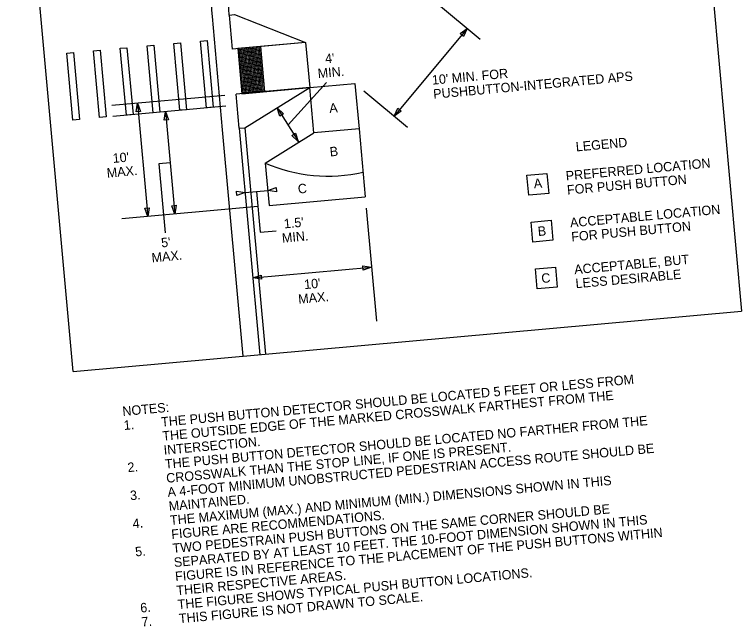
# Model space of a CAD drawing. Extents: x 1277218 to 1279252, y 196905 to 197529.
# Drawn here: x 1278337.8 to 1278669.3, y 196934.2 to 197213 of the extents above; entities that cross this region are included whole.
import ezdxf

# ---------------------------------------------------------------- set-up
doc = ezdxf.new("R2010")
doc.units = 0
doc.layers.add('C-TOPO-SURF-VOID', color=7, linetype='Continuous')

msp = doc.modelspace()

# ---------------------------------------------------------------- linework, layer by layer
at = {"layer": 'C-TOPO-SURF-VOID'}
for p, q in [((1278642.58, 197372.36), (1278669.26, 197077.94)), ((1278364.51, 197050.32), (1278337.83, 197344.75)), ((1278530.19, 197218.42), (1278550.08, 197201.84)), ((1278435.61, 197212.8), (1278438.19, 197213.04)), ((1278438.19, 197213.04), (1278470.54, 197200.37)), ((1278427.87, 197212.1), (1278432.54, 197160.51)), ((1278435.61, 197212.8), (1278437.01, 197197.33)), ((1278544.26, 197206.69), (1278510.91, 197166.7)), ((1278470.54, 197200.37), (1278437.01, 197197.33)), ((1278470.54, 197200.37), (1278439.59, 197197.56)), ((1278470.54, 197200.37), (1278472.41, 197179.73)), ((1278439.59, 197197.56), (1278441.46, 197176.92)), ((1278449.91, 197198.5), (1278451.78, 197177.86)), ((1278462.51, 197162.71), (1278480.12, 197182.07)), ((1278472.41, 197179.73), (1278438.88, 197176.69)), ((1278440.28, 197161.21), (1278438.88, 197176.69)), ((1278441.46, 197176.92), (1278472.41, 197179.73)), ((1278442.86, 197161.45), (1278472.41, 197179.73)), ((1278497.05, 197178.26), (1278516.94, 197161.68)), ((1278433.72, 197176.22), (1278382.13, 197171.55)), ((1278434.17, 197171.3), (1278382.58, 197166.63)), ((1278393.93, 197172.62), (1278398.61, 197121.03)), ((1278457.64, 197170.59), (1278467.39, 197154.83)), ((1278406.66, 197168.81), (1278410.89, 197122.14)), ((1278432.54, 197160.51), (1278441.89, 197057.33)), ((1278440.28, 197161.21), (1278442.86, 197161.45)), ((1278440.28, 197161.21), (1278449.63, 197058.03)), ((1278442.86, 197161.45), (1278452.21, 197058.27)), ((1278494.92, 197160.96), (1278497.72, 197130.01)), ((1278452.12, 197145.38), (1278474.28, 197159.09)), ((1278452.12, 197145.38), (1278453.87, 197126.04)), ((1278442.94, 197131.92), (1278453.26, 197132.85)), ((1278453.87, 197126.04), (1278497.72, 197130.01)), ((1278448.71, 197125.57), (1278386.81, 197119.96)), ((1278498.19, 197124.85), (1278502.87, 197073.26)), ((1278446.46, 197093.01), (1278500.63, 197097.92)), ((1278364.51, 197050.32), (1278669.26, 197077.94))]:
    msp.add_line(p, q, dxfattribs=at)
for points in [[(1278541.03, 197204.33), (1278544.26, 197206.69), (1278542.52, 197203.09)], [(1278410.43, 197199.88), (1278413.48, 197200.15), (1278416.24, 197169.68), (1278413.19, 197169.4)], [(1278422.62, 197200.98), (1278425.67, 197201.26), (1278428.43, 197170.78), (1278425.38, 197170.51)], [(1278373.86, 197196.56), (1278376.91, 197196.84), (1278379.67, 197166.37), (1278376.62, 197166.09)], [(1278386.05, 197197.67), (1278389.1, 197197.94), (1278391.86, 197167.47), (1278388.81, 197167.19)], [(1278398.24, 197198.77), (1278401.29, 197199.05), (1278404.05, 197168.57), (1278401, 197168.3)], [(1278361.67, 197195.46), (1278364.72, 197195.74), (1278367.48, 197165.26), (1278364.43, 197164.98)], [(1278472.41, 197179.73), (1278493.05, 197181.6), (1278494.92, 197160.96), (1278474.28, 197159.09)], [(1278393.32, 197168.66), (1278393.93, 197172.62), (1278395.25, 197168.84)], [(1278458.86, 197166.77), (1278457.64, 197170.59), (1278460.51, 197167.8)], [(1278514.15, 197169.06), (1278510.91, 197166.7), (1278512.66, 197170.31)], [(1278406.05, 197164.85), (1278406.66, 197168.81), (1278407.98, 197165.03)], [(1278465.97, 197158.96), (1278467.19, 197155.15), (1278464.32, 197157.94)], [(1278571.42, 197139.81), (1278580.57, 197140.64), (1278581.39, 197131.5), (1278572.25, 197130.67)], [(1278457.21, 197132.23), (1278453.26, 197132.85), (1278457.04, 197134.17)], [(1278438.98, 197132.53), (1278442.94, 197131.92), (1278439.16, 197130.6)], [(1278399.22, 197124.98), (1278398.61, 197121.03), (1278397.29, 197124.81)], [(1278411.51, 197126.1), (1278410.89, 197122.14), (1278409.57, 197125.92)], [(1278573.36, 197118.48), (1278582.5, 197119.31), (1278583.33, 197110.17), (1278574.19, 197109.34)], [(1278496.68, 197098.54), (1278500.63, 197097.92), (1278496.85, 197096.6)], [(1278575.29, 197097.15), (1278584.43, 197097.98), (1278585.26, 197088.83), (1278576.12, 197088)], [(1278450.42, 197092.4), (1278446.46, 197093.01), (1278450.24, 197094.33)]]:
    msp.add_lwpolyline(points, close=True, dxfattribs=at)
for points in [[(1278408.78, 197145.48), (1278403.62, 197145.01), (1278406.46, 197113.63)], [(1278448.1, 197132.38), (1278449.78, 197113.86), (1278457.07, 197114.52)]]:
    msp.add_lwpolyline(points, dxfattribs=at)
for centre in [(1278440.25, 197197.05), (1278440.31, 197196.44), (1278440.86, 197197.1), (1278440.92, 197196.49), (1278441.47, 197197.16), (1278441.52, 197196.55), (1278442.08, 197197.21), (1278442.13, 197196.61), (1278442.69, 197197.27), (1278442.74, 197196.66), (1278443.3, 197197.33), (1278443.35, 197196.72), (1278443.91, 197197.38), (1278443.96, 197196.77), (1278444.52, 197197.44), (1278444.57, 197196.83), (1278444.63, 197196.22), (1278445.13, 197197.49), (1278445.18, 197196.88), (1278445.24, 197196.27), (1278445.74, 197197.55), (1278445.79, 197196.94), (1278445.85, 197196.33), (1278446.35, 197197.6), (1278446.4, 197196.99), (1278446.46, 197196.38), (1278446.95, 197197.66), (1278447.01, 197197.05), (1278447.07, 197196.44), (1278447.56, 197197.71), (1278447.62, 197197.1), (1278447.67, 197196.49), (1278448.17, 197197.77), (1278448.23, 197197.16), (1278448.28, 197196.55), (1278448.78, 197197.82), (1278448.84, 197197.21), (1278448.89, 197196.6), (1278449.39, 197197.88), (1278449.45, 197197.27), (1278449.5, 197196.66), (1278440.36, 197195.83), (1278440.42, 197195.22), (1278440.47, 197194.61), (1278440.53, 197194), (1278440.58, 197193.39), (1278440.97, 197195.89), (1278441.03, 197195.28), (1278441.08, 197194.67), (1278441.14, 197194.06), (1278441.19, 197193.45), (1278441.58, 197195.94), (1278441.63, 197195.33), (1278441.69, 197194.72), (1278441.75, 197194.11), (1278441.8, 197193.5), (1278441.86, 197192.89), (1278442.19, 197196), (1278442.24, 197195.39), (1278442.3, 197194.78), (1278442.35, 197194.17), (1278442.41, 197193.56), (1278442.47, 197192.95), (1278442.8, 197196.05), (1278442.85, 197195.44), (1278442.91, 197194.83), (1278442.96, 197194.22), (1278443.02, 197193.61), (1278443.07, 197193), (1278443.41, 197196.11), (1278443.46, 197195.5), (1278443.52, 197194.89), (1278443.57, 197194.28), (1278443.63, 197193.67), (1278443.68, 197193.06), (1278444.02, 197196.16), (1278444.07, 197195.55), (1278444.13, 197194.94), (1278444.18, 197194.33), (1278444.24, 197193.72), (1278444.29, 197193.11), (1278444.68, 197195.61), (1278444.74, 197195), (1278444.79, 197194.39), (1278444.85, 197193.78), (1278444.9, 197193.17), (1278445.29, 197195.66), (1278445.35, 197195.05), (1278445.4, 197194.44), (1278445.46, 197193.83), (1278445.51, 197193.22), (1278445.9, 197195.72), (1278445.96, 197195.11), (1278446.01, 197194.5), (1278446.07, 197193.89), (1278446.12, 197193.28), (1278446.51, 197195.77), (1278446.57, 197195.16), (1278446.62, 197194.55), (1278446.68, 197193.94), (1278446.73, 197193.34), (1278447.12, 197195.83), (1278447.18, 197195.22), (1278447.23, 197194.61), (1278447.29, 197194), (1278447.34, 197193.39), (1278447.73, 197195.88), (1278447.79, 197195.27), (1278447.84, 197194.66), (1278447.9, 197194.06), (1278447.95, 197193.45), (1278448.34, 197195.94), (1278448.39, 197195.33), (1278448.45, 197194.72), (1278448.51, 197194.11), (1278448.56, 197193.5), (1278448.62, 197192.89), (1278448.95, 197195.99), (1278449, 197195.38), (1278449.06, 197194.78), (1278449.11, 197194.17), (1278449.17, 197193.56), (1278449.23, 197192.95), (1278449.56, 197196.05), (1278449.61, 197195.44), (1278449.67, 197194.83), (1278449.72, 197194.22), (1278449.78, 197193.61), (1278449.83, 197193), (1278440.64, 197192.78), (1278440.69, 197192.17), (1278440.75, 197191.56), (1278440.8, 197190.95), (1278440.86, 197190.34), (1278440.91, 197189.74), (1278441.25, 197192.84), (1278441.3, 197192.23), (1278441.36, 197191.62), (1278441.41, 197191.01), (1278441.47, 197190.4), (1278441.52, 197189.79), (1278441.91, 197192.28), (1278441.97, 197191.67), (1278442.02, 197191.06), (1278442.08, 197190.46), (1278442.13, 197189.85), (1278442.52, 197192.34), (1278442.58, 197191.73), (1278442.63, 197191.12), (1278442.69, 197190.51), (1278442.74, 197189.9), (1278443.13, 197192.39), (1278443.19, 197191.78), (1278443.24, 197191.18), (1278443.3, 197190.57), (1278443.35, 197189.96), (1278443.74, 197192.45), (1278443.79, 197191.84), (1278443.85, 197191.23), (1278443.91, 197190.62), (1278443.96, 197190.01), (1278444.35, 197192.5), (1278444.4, 197191.9), (1278444.46, 197191.29), (1278444.51, 197190.68), (1278444.57, 197190.07), (1278444.96, 197192.56), (1278445.01, 197191.95), (1278445.07, 197191.34), (1278445.12, 197190.73), (1278445.18, 197190.12), (1278445.57, 197192.62), (1278445.62, 197192.01), (1278445.68, 197191.4), (1278445.73, 197190.79), (1278445.79, 197190.18), (1278445.84, 197189.57), (1278446.18, 197192.67), (1278446.23, 197192.06), (1278446.29, 197191.45), (1278446.34, 197190.84), (1278446.4, 197190.23), (1278446.45, 197189.62), (1278446.79, 197192.73), (1278446.84, 197192.12), (1278446.9, 197191.51), (1278446.95, 197190.9), (1278447.01, 197190.29), (1278447.06, 197189.68), (1278447.4, 197192.78), (1278447.45, 197192.17), (1278447.51, 197191.56), (1278447.56, 197190.95), (1278447.62, 197190.34), (1278447.67, 197189.73), (1278448.01, 197192.84), (1278448.06, 197192.23), (1278448.12, 197191.62), (1278448.17, 197191.01), (1278448.23, 197190.4), (1278448.28, 197189.79), (1278448.67, 197192.28), (1278448.73, 197191.67), (1278448.78, 197191.06), (1278448.84, 197190.45), (1278448.89, 197189.84), (1278449.28, 197192.34), (1278449.34, 197191.73), (1278449.39, 197191.12), (1278449.45, 197190.51), (1278449.5, 197189.9), (1278449.89, 197192.39), (1278449.95, 197191.78), (1278450, 197191.17), (1278450.06, 197190.56), (1278450.11, 197189.95), (1278440.97, 197189.13), (1278441.02, 197188.52), (1278441.08, 197187.91), (1278441.13, 197187.3), (1278441.19, 197186.69), (1278441.58, 197189.18), (1278441.63, 197188.57), (1278441.69, 197187.96), (1278441.74, 197187.35), (1278441.8, 197186.74), (1278442.19, 197189.24), (1278442.24, 197188.63), (1278442.3, 197188.02), (1278442.35, 197187.41), (1278442.41, 197186.8), (1278442.8, 197189.29), (1278442.85, 197188.68), (1278442.91, 197188.07), (1278442.96, 197187.46), (1278443.02, 197186.85), (1278443.41, 197189.35), (1278443.46, 197188.74), (1278443.52, 197188.13), (1278443.57, 197187.52), (1278443.63, 197186.91), (1278443.68, 197186.3), (1278444.02, 197189.4), (1278444.07, 197188.79), (1278444.13, 197188.18), (1278444.18, 197187.57), (1278444.24, 197186.96), (1278444.29, 197186.35), (1278444.63, 197189.46), (1278444.68, 197188.85), (1278444.74, 197188.24), (1278444.79, 197187.63), (1278444.85, 197187.02), (1278444.9, 197186.41), (1278445.23, 197189.51), (1278445.29, 197188.9), (1278445.35, 197188.29), (1278445.4, 197187.68), (1278445.46, 197187.07), (1278445.51, 197186.46), (1278445.9, 197188.96), (1278445.95, 197188.35), (1278446.01, 197187.74), (1278446.07, 197187.13), (1278446.12, 197186.52), (1278446.51, 197189.01), (1278446.56, 197188.4), (1278446.62, 197187.79), (1278446.67, 197187.18), (1278446.73, 197186.58), (1278447.12, 197189.07), (1278447.17, 197188.46), (1278447.23, 197187.85), (1278447.28, 197187.24), (1278447.34, 197186.63), (1278447.73, 197189.12), (1278447.78, 197188.51), (1278447.84, 197187.9), (1278447.89, 197187.3), (1278447.95, 197186.69), (1278448.34, 197189.18), (1278448.39, 197188.57), (1278448.45, 197187.96), (1278448.5, 197187.35), (1278448.56, 197186.74), (1278448.95, 197189.23), (1278449, 197188.62), (1278449.06, 197188.02), (1278449.11, 197187.41), (1278449.17, 197186.8), (1278449.56, 197189.29), (1278449.61, 197188.68), (1278449.67, 197188.07), (1278449.72, 197187.46), (1278449.78, 197186.85), (1278450.17, 197189.34), (1278450.22, 197188.74), (1278450.28, 197188.13), (1278450.33, 197187.52), (1278450.39, 197186.91), (1278450.44, 197186.3), (1278441.24, 197186.08), (1278441.3, 197185.47), (1278441.35, 197184.86), (1278441.41, 197184.25), (1278441.47, 197183.64), (1278441.52, 197183.03), (1278441.85, 197186.13), (1278441.91, 197185.52), (1278441.96, 197184.91), (1278442.02, 197184.31), (1278442.07, 197183.7), (1278442.13, 197183.09), (1278442.46, 197186.19), (1278442.52, 197185.58), (1278442.57, 197184.97), (1278442.63, 197184.36), (1278442.68, 197183.75), (1278442.74, 197183.14), (1278443.07, 197186.24), (1278443.13, 197185.63), (1278443.18, 197185.03), (1278443.24, 197184.42), (1278443.29, 197183.81), (1278443.35, 197183.2), (1278443.74, 197185.69), (1278443.79, 197185.08), (1278443.85, 197184.47), (1278443.9, 197183.86), (1278443.96, 197183.25), (1278444.35, 197185.75), (1278444.4, 197185.14), (1278444.46, 197184.53), (1278444.51, 197183.92), (1278444.57, 197183.31), (1278444.96, 197185.8), (1278445.01, 197185.19), (1278445.07, 197184.58), (1278445.12, 197183.97), (1278445.18, 197183.36), (1278445.57, 197185.86), (1278445.62, 197185.25), (1278445.68, 197184.64), (1278445.73, 197184.03), (1278445.79, 197183.42), (1278446.18, 197185.91), (1278446.23, 197185.3), (1278446.29, 197184.69), (1278446.34, 197184.08), (1278446.4, 197183.47), (1278446.79, 197185.97), (1278446.84, 197185.36), (1278446.9, 197184.75), (1278446.95, 197184.14), (1278447.01, 197183.53), (1278447.39, 197186.02), (1278447.45, 197185.41), (1278447.51, 197184.8), (1278447.56, 197184.19), (1278447.62, 197183.58), (1278447.67, 197182.97), (1278448, 197186.08), (1278448.06, 197185.47), (1278448.11, 197184.86), (1278448.17, 197184.25), (1278448.23, 197183.64), (1278448.28, 197183.03), (1278448.61, 197186.13), (1278448.67, 197185.52), (1278448.72, 197184.91), (1278448.78, 197184.3), (1278448.83, 197183.69), (1278448.89, 197183.08), (1278449.22, 197186.19), (1278449.28, 197185.58), (1278449.33, 197184.97), (1278449.39, 197184.36), (1278449.44, 197183.75), (1278449.5, 197183.14), (1278449.83, 197186.24), (1278449.89, 197185.63), (1278449.94, 197185.02), (1278450, 197184.41), (1278450.05, 197183.8), (1278450.11, 197183.19), (1278450.5, 197185.69), (1278450.55, 197185.08), (1278450.61, 197184.47), (1278450.66, 197183.86), (1278450.72, 197183.25), (1278441.58, 197182.42), (1278441.63, 197181.81), (1278441.69, 197181.2), (1278441.74, 197180.59), (1278441.8, 197179.98), (1278442.19, 197182.48), (1278442.24, 197181.87), (1278442.3, 197181.26), (1278442.35, 197180.65), (1278442.41, 197180.04), (1278442.79, 197182.53), (1278442.85, 197181.92), (1278442.91, 197181.31), (1278442.96, 197180.7), (1278443.02, 197180.09), (1278443.4, 197182.59), (1278443.46, 197181.98), (1278443.51, 197181.37), (1278443.57, 197180.76), (1278443.63, 197180.15), (1278444.01, 197182.64), (1278444.07, 197182.03), (1278444.12, 197181.42), (1278444.18, 197180.81), (1278444.23, 197180.2), (1278444.62, 197182.7), (1278444.68, 197182.09), (1278444.73, 197181.48), (1278444.79, 197180.87), (1278444.84, 197180.26), (1278444.9, 197179.65), (1278445.23, 197182.75), (1278445.29, 197182.14), (1278445.34, 197181.53), (1278445.4, 197180.92), (1278445.45, 197180.31), (1278445.51, 197179.71), (1278445.84, 197182.81), (1278445.9, 197182.2), (1278445.95, 197181.59), (1278446.01, 197180.98), (1278446.06, 197180.37), (1278446.12, 197179.76), (1278446.45, 197182.86), (1278446.51, 197182.25), (1278446.56, 197181.64), (1278446.62, 197181.03), (1278446.67, 197180.43), (1278446.73, 197179.82), (1278447.06, 197182.92), (1278447.12, 197182.31), (1278447.17, 197181.7), (1278447.23, 197181.09), (1278447.28, 197180.48), (1278447.34, 197179.87), (1278447.73, 197182.36), (1278447.78, 197181.75), (1278447.84, 197181.15), (1278447.89, 197180.54), (1278447.95, 197179.93), (1278448.34, 197182.42), (1278448.39, 197181.81), (1278448.45, 197181.2), (1278448.5, 197180.59), (1278448.56, 197179.98), (1278448.95, 197182.47), (1278449, 197181.87), (1278449.06, 197181.26), (1278449.11, 197180.65), (1278449.17, 197180.04), (1278449.55, 197182.53), (1278449.61, 197181.92), (1278449.66, 197181.31), (1278449.72, 197180.7), (1278449.78, 197180.09), (1278450.16, 197182.59), (1278450.22, 197181.98), (1278450.27, 197181.37), (1278450.33, 197180.76), (1278450.38, 197180.15), (1278450.77, 197182.64), (1278450.83, 197182.03), (1278450.88, 197181.42), (1278450.94, 197180.81), (1278450.99, 197180.2), (1278441.85, 197179.37), (1278441.91, 197178.76), (1278441.96, 197178.15), (1278442.02, 197177.55), (1278442.46, 197179.43), (1278442.52, 197178.82), (1278442.57, 197178.21), (1278442.63, 197177.6), (1278443.07, 197179.48), (1278443.13, 197178.87), (1278443.18, 197178.27), (1278443.24, 197177.66), (1278443.68, 197179.54), (1278443.74, 197178.93), (1278443.79, 197178.32), (1278443.85, 197177.71), (1278444.29, 197179.59), (1278444.35, 197178.99), (1278444.4, 197178.38), (1278444.46, 197177.77), (1278444.95, 197179.04), (1278445.01, 197178.43), (1278445.07, 197177.82), (1278445.56, 197179.1), (1278445.62, 197178.49), (1278445.67, 197177.88), (1278446.17, 197179.15), (1278446.23, 197178.54), (1278446.28, 197177.93), (1278446.78, 197179.21), (1278446.84, 197178.6), (1278446.89, 197177.99), (1278447.39, 197179.26), (1278447.45, 197178.65), (1278447.5, 197178.04), (1278448, 197179.32), (1278448.06, 197178.71), (1278448.11, 197178.1), (1278448.61, 197179.37), (1278448.67, 197178.76), (1278448.72, 197178.15), (1278449.22, 197179.43), (1278449.28, 197178.82), (1278449.33, 197178.21), (1278449.83, 197179.48), (1278449.89, 197178.87), (1278449.94, 197178.26), (1278450.44, 197179.54), (1278450.5, 197178.93), (1278450.55, 197178.32), (1278451.05, 197179.59), (1278451.1, 197178.98), (1278451.16, 197178.37)]:
    msp.add_circle(centre, 0.115, dxfattribs=at)
for centre, radius, start, end in [((1278489.74, 197218.08), 62.16, 94.7692, 185.5865), ((1278489.74, 197218.08), 54.39, 94.7692, 185.5865), ((1278480.87, 197211.93), 72.5, 246.6378, 282.6239)]:
    msp.add_arc(centre, radius, start, end, dxfattribs=at)

# ---------------------------------------------------------------- texts
for s, height, p in [("4'", 4.284, (1278479.61, 197190.78)), ('MIN.', 4.284, (1278476.25, 197184.02)), ("10' MIN. FOR ", 4.2839, (1278528.33, 197181.07)), ('PUSHBUTTON-INTEGRATED APS', 4.2839, (1278528.91, 197174.67)), ('A', 4.28, (1278481.5, 197168.21)), ('LEGEND', 4.284, (1278593.91, 197150.64)), ("10'", 4.284, (1278382.76, 197145.38)), ('B', 4.28, (1278481.73, 197148.35)), ('PREFERRED LOCATION ', 4.2839, (1278589.35, 197137.37)), ('MAX.', 4.284, (1278380.06, 197138.69)), ('FOR PUSH BUTTON', 4.2839, (1278589.93, 197130.97)), ('A', 4.28, (1278574.72, 197133.81)), ('C', 4.28, (1278467.19, 197131.43)), ('ACCEPTABLE LOCATION ', 4.2839, (1278591.28, 197116.03)), ("1.5'", 4.284, (1278460.81, 197115.58)), ('FOR PUSH BUTTON', 4.2839, (1278591.86, 197109.63)), ('MIN.', 4.284, (1278459.93, 197109.05)), ('B', 4.28, (1278576.58, 197112.08)), ("5'", 4.284, (1278404.86, 197106.91)), ('MAX.', 4.284, (1278400.5, 197100.06)), ('ACCEPTABLE, BUT ', 4.2839, (1278593.21, 197094.7)), ('LESS DESIRABLE', 4.2839, (1278593.79, 197088.3)), ('C', 4.28, (1278578.2, 197090.66)), ("10'", 4.284, (1278470.06, 197087.9)), ('MAX.', 4.284, (1278467.36, 197081.21)), ('THE PUSH BUTTON DETECTOR SHOULD BE LOCATED 5 FEET OR LESS FROM ', 4.2839, (1278404.86, 197025.24)), ('THE OUTSIDE EDGE OF THE MARKED CROSSWALK FARTHEST FROM THE ', 4.2839, (1278405.44, 197018.84)), ('NOTES:', 4.284, (1278387.21, 197030.1)), ('1.', 4.284, (1278387.79, 197023.7)), ('THE PUSH BUTTON DETECTOR SHOULD BE LOCATED NO FARTHER FROM THE ', 4.2839, (1278406.6, 197006.04)), ('INTERSECTION.', 4.2839, (1278406.02, 197012.44)), ('CROSSWALK THAN THE STOP LINE, IF ONE IS PRESENT.', 4.2839, (1278407.18, 196999.64)), ('A 4-FOOT MINIMUM UNOBSTRUCTED PEDESTRIAN ACCESS ROUTE SHOULD BE ', 4.2839, (1278407.76, 196993.24)), ('2.', 4.284, (1278389.53, 197004.5)), ('THE MAXIMUM (MAX.) AND MINIMUM (MIN.) DIMENSIONS SHOWN IN THIS ', 4.2839, (1278408.92, 196980.45)), ('3.', 4.284, (1278390.69, 196991.7)), ('MAINTAINED.', 4.2839, (1278408.34, 196986.85)), ('TWO PEDESTRAIN PUSH BUTTONS ON THE SAME CORNER SHOULD BE ', 4.2839, (1278410.08, 196967.65)), ('FIGURE ARE RECOMMENDATIONS.', 4.2839, (1278409.5, 196974.05)), ('SEPARATED BY AT LEAST 10 FEET. THE 10-FOOT DIMENSION SHOWN IN THIS ', 4.2839, (1278410.66, 196961.25)), ('4.', 4.284, (1278391.85, 196978.9)), ('FIGURE IS IN REFERENCE TO THE PLACEMENT OF THE PUSH BUTTONS WITHIN ', 4.2839, (1278411.24, 196954.85)), ('5.', 4.284, (1278393.01, 196966.1)), ('THEIR RESPECTIVE AREAS.', 4.2839, (1278411.82, 196948.45)), ('THE FIGURE SHOWS TYPICAL PUSH BUTTON LOCATIONS.', 4.2839, (1278412.4, 196942.05)), ('THIS FIGURE IS NOT DRAWN TO SCALE.', 4.2839, (1278412.98, 196935.65)), ('6.', 4.284, (1278395.33, 196940.5)), ('7.', 4.284, (1278395.91, 196934.1))]:
    msp.add_text(s, height=height, rotation=5.1779, dxfattribs=at).set_placement(p)

doc.saveas('drawing.dxf')
